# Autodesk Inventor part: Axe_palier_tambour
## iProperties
Shininess: 64.0
Length Units: 11269
Angle Units: 11279
Time Units: 11290
Mass Units: 11283
Length Display Precision: 3
Angle Display Precision: 2
Compacted: True
Part Number: Axe_palier_tambour
Document SubType Name: Modeling
Created: 2008-02
Material: Acier (alliage faible hypertrempé)
Designer: Pascal
Density: 0.0
Volumn: 0.0
Area: 0.0
PropertySet Name: Model Information
Control State: 0
Master: False
Checked Out: False
DESIGNATION: pièce
Author: Pascal
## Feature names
1. Révolution1 [Revolution]
2. Congé1 [Fillet]
